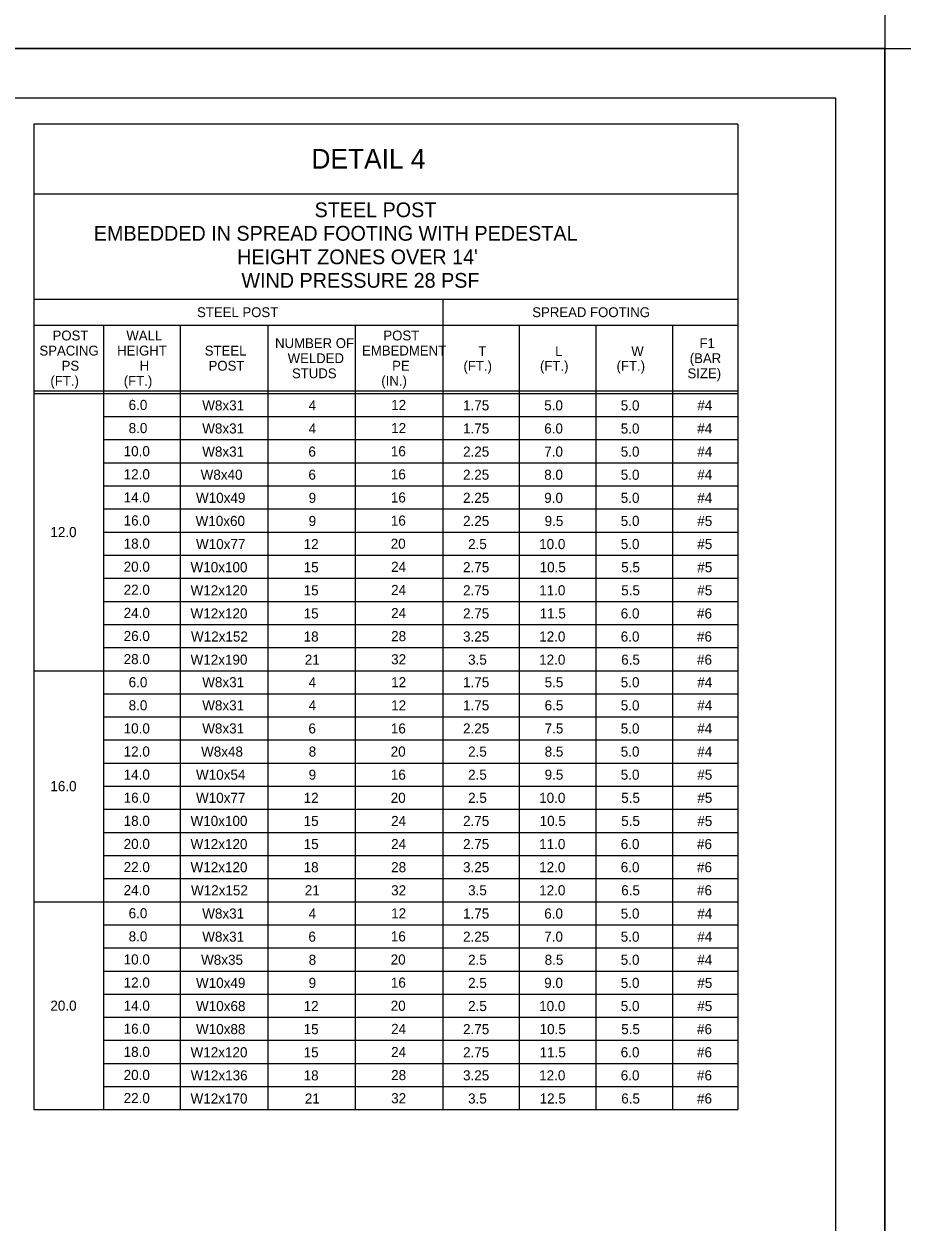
# Model space of a CAD drawing. Extents: x 3475 to 6558, y -3780 to 1166.
# Drawn here: x 5180.9 to 5448.6, y -2161.9 to -1796.8 of the extents above; entities that cross this region are included whole.
import ezdxf

# ---------------------------------------------------------------- set-up
doc = ezdxf.new("R2010")
doc.units = 0
for name, color, linetype in [('1', 7, 'Continuous'), ('2', 7, 'Continuous'), ('PLT-BNDY', 7, 'Continuous')]:
    doc.layers.add(name, color=color, linetype=linetype)

msp = doc.modelspace()

# ---------------------------------------------------------------- linework, layer by layer
at = {"layer": '1'}
for p, q in [((5183.95, -1827.3), (5183.95, -2127.63)), ((5398.61, -1827.3), (5183.95, -1827.3)), ((5398.61, -1827.3), (5398.61, -2127.63)), ((5398.61, -1848.64), (5183.95, -1848.64)), ((5183.95, -1880.64), (5398.61, -1880.64)), ((5308.61, -1880.64), (5308.61, -2127.63)), ((5183.95, -1888.64), (5251.95, -1888.64)), ((5183.95, -1888.64), (5398.61, -1888.64)), ((5205.28, -2127.63), (5205.28, -1888.64)), ((5228.61, -1888.64), (5228.61, -2127.63)), ((5255.28, -1888.64), (5255.28, -2127.63)), ((5281.95, -1888.64), (5281.95, -2127.63)), ((5331.95, -1888.64), (5331.95, -2127.63)), ((5355.28, -1888.64), (5355.28, -2127.63)), ((5378.61, -1888.64), (5378.61, -2127.63)), ((5183.95, -1908.64), (5398.61, -1908.64)), ((5183.95, -1909.39), (5398.61, -1909.39)), ((5205.28, -1916.43), (5398.61, -1916.43)), ((5205.28, -1923.47), (5398.61, -1923.47)), ((5205.28, -1930.51), (5398.61, -1930.51)), ((5205.28, -1937.55), (5398.61, -1937.55)), ((5205.28, -1944.59), (5398.61, -1944.59)), ((5205.28, -1951.63), (5398.61, -1951.63)), ((5205.28, -1958.67), (5398.61, -1958.67)), ((5205.28, -1965.71), (5398.61, -1965.71)), ((5205.28, -1972.75), (5398.61, -1972.75)), ((5205.28, -1979.79), (5398.61, -1979.79)), ((5205.28, -1986.83), (5398.61, -1986.83)), ((5183.95, -1993.87), (5398.61, -1993.87)), ((5205.28, -2000.91), (5398.61, -2000.91)), ((5205.28, -2007.95), (5398.61, -2007.95)), ((5205.28, -2014.99), (5398.61, -2014.99)), ((5205.28, -2022.03), (5398.61, -2022.03)), ((5205.28, -2029.07), (5398.61, -2029.07)), ((5205.28, -2036.11), (5398.61, -2036.11)), ((5205.28, -2043.15), (5398.61, -2043.15)), ((5205.28, -2050.19), (5398.61, -2050.19)), ((5205.28, -2057.23), (5398.61, -2057.23)), ((5183.95, -2064.27), (5398.61, -2064.27)), ((5205.28, -2071.31), (5398.61, -2071.31)), ((5205.28, -2078.35), (5398.61, -2078.35)), ((5205.28, -2085.39), (5398.61, -2085.39)), ((5205.28, -2092.43), (5398.61, -2092.43)), ((5205.28, -2099.47), (5398.61, -2099.47)), ((5205.28, -2106.51), (5398.61, -2106.51)), ((5205.28, -2113.55), (5398.61, -2113.55)), ((5205.28, -2120.59), (5398.61, -2120.59)), ((5183.95, -2127.63), (5398.61, -2127.63))]:
    msp.add_line(p, q, dxfattribs=at)
at = {"layer": '2'}
for p, q in [((4642.34, -1819.31), (5428.34, -1819.31)), ((5428.34, -1819.31), (5428.34, -2383.31))]:
    msp.add_line(p, q, dxfattribs=at)
at = {"layer": 'PLT-BNDY'}
for points in [[(4602.34, -1210.31), (5443.34, -1210.31), (5443.34, -1804.31), (4602.34, -1804.31)], [(4602.34, -1804.31), (5443.34, -1804.31), (5443.34, -2398.31), (4602.34, -2398.31)], [(5443.34, -1804.31), (6284.34, -1804.31), (6284.34, -2398.31), (5443.34, -2398.31)]]:
    msp.add_lwpolyline(points, close=True, dxfattribs=at)

# ---------------------------------------------------------------- texts
at = {"layer": '1'}
for s, height, p in [('DETAIL 4', 6, (5268.58, -1840.89)), ('STEEL POST', 4.5, (5269.54, -1855.69)), ('EMBEDDED IN SPREAD FOOTING WITH PEDESTAL', 4.5001, (5202.25, -1862.85)), ("HEIGHT ZONES OVER 14'", 4.5001, (5245.93, -1870.02)), ('WIND PRESSURE 28 PSF', 4.5001, (5247.24, -1877.19)), ('STEEL POST', 3, (5233.72, -1886.14)), ('SPREAD FOOTING', 3, (5335.9, -1886.14)), ('POST', 3, (5189.67, -1893.24)), ('WALL', 3, (5212.16, -1893.24)), ('POST', 3, (5290.52, -1893.24)), ('NUMBER OF', 3, (5257.5, -1895.56)), ('F1', 3, (5386.87, -1895.56)), ('SPACING', 3, (5185.67, -1897.84)), ('HEIGHT', 3, (5209.34, -1897.84)), ('STEEL', 3, (5236.05, -1897.86)), ('WELDED', 3, (5261.34, -1900.16)), ('EMBEDMENT', 3, (5284.02, -1897.84)), ('T', 3, (5319.42, -1898)), ('L', 3, (5342.88, -1898)), ('W', 3, (5366.08, -1898)), ('(BAR', 3, (5383.91, -1900.16)), ('PS', 3, (5192.43, -1902.44)), ('H', 3, (5216.21, -1902.44)), ('POST', 3, (5237.22, -1902.46)), ('STUDS', 3, (5262.65, -1904.76)), ('PE', 3, (5293.18, -1902.44)), ('(FT.)', 3, (5314.92, -1902.5)), ('(FT.)', 3, (5338.25, -1902.5)), ('(FT.)', 3, (5361.59, -1902.5)), ('SIZE)', 3, (5383.21, -1904.76)), ('(FT.)', 3, (5189, -1907.04)), ('(FT.)', 3, (5211.37, -1907.04)), ('(IN.)', 3, (5289.88, -1907.04)), ('6.0', 3.07, (5212.86, -1914.44)), ('W8x31', 3.07, (5235.29, -1914.56)), ('4', 3.07, (5267.74, -1914.56)), ('12', 3.07, (5292.88, -1914.44)), ('1.75', 3.07, (5314.8, -1914.56)), ('5.0', 3.07, (5339.54, -1914.56)), ('5.0', 3.07, (5362.87, -1914.58)), ('#4', 3.07, (5386.21, -1914.56)), ('8.0', 3.07, (5212.86, -1921.48)), ('W8x31', 3.07, (5235.29, -1921.6)), ('4', 3.07, (5267.74, -1921.6)), ('12', 3.07, (5292.88, -1921.49)), ('1.75', 3.07, (5314.8, -1921.6)), ('6.0', 3.07, (5339.54, -1921.6)), ('5.0', 3.07, (5362.87, -1921.62)), ('#4', 3.07, (5386.21, -1921.6)), ('10.0', 3.07, (5211.34, -1928.52)), ('W8x31', 3.07, (5235.29, -1928.65)), ('6', 3.07, (5267.66, -1928.65)), ('16', 3.07, (5292.79, -1928.54)), ('2.25', 3.07, (5314.8, -1928.65)), ('7.0', 3.07, (5339.54, -1928.65)), ('5.0', 3.07, (5362.87, -1928.66)), ('#4', 3.07, (5386.21, -1928.65)), ('12.0', 3.07, (5211.34, -1935.56)), ('W8x40', 3.07, (5234.8, -1935.69)), ('6', 3.07, (5267.66, -1935.69)), ('16', 3.07, (5292.79, -1935.58)), ('2.25', 3.07, (5314.8, -1935.69)), ('8.0', 3.07, (5339.54, -1935.69)), ('5.0', 3.07, (5362.87, -1935.7)), ('#4', 3.07, (5386.21, -1935.69)), ('14.0', 3.07, (5211.34, -1942.6)), ('W10x49', 3.07, (5233.39, -1942.74)), ('9', 3.07, (5267.73, -1942.74)), ('16', 3.07, (5292.79, -1942.63)), ('2.25', 3.07, (5314.8, -1942.74)), ('9.0', 3.07, (5339.54, -1942.74)), ('5.0', 3.07, (5362.87, -1942.74)), ('#4', 3.07, (5386.21, -1942.74)), ('16.0', 3.07, (5211.34, -1949.64)), ('W10x60', 3.07, (5233.27, -1949.78)), ('9', 3.07, (5267.73, -1949.78)), ('16', 3.07, (5292.79, -1949.67)), ('2.25', 3.07, (5314.8, -1949.78)), ('9.5', 3.07, (5339.67, -1949.78)), ('5.0', 3.07, (5362.87, -1949.78)), ('#5', 3.07, (5386.21, -1949.78)), ('12.0', 3.07, (5189, -1953.16)), ('18.0', 3.07, (5211.34, -1956.68)), ('W10x77', 3.07, (5233.4, -1956.83)), ('12', 3.07, (5266.21, -1956.83)), ('20', 3.07, (5292.74, -1956.71)), ('2.5', 3.07, (5316.34, -1956.83)), ('10.0', 3.07, (5338, -1956.83)), ('5.0', 3.07, (5362.87, -1956.83)), ('#5', 3.07, (5386.21, -1956.83)), ('20.0', 3.07, (5211.34, -1963.72)), ('W10x100', 3.07, (5231.73, -1963.87)), ('15', 3.07, (5266.21, -1963.87)), ('24', 3.07, (5292.88, -1963.77)), ('2.75', 3.07, (5314.8, -1963.87)), ('10.5', 3.07, (5338.14, -1963.87)), ('5.5', 3.07, (5363.01, -1963.87)), ('#5', 3.07, (5386.21, -1963.87)), ('22.0', 3.07, (5211.34, -1970.76)), ('24', 3.07, (5292.88, -1970.81)), ('W12x120', 3.07, (5231.73, -1970.91)), ('15', 3.07, (5266.21, -1970.91)), ('2.75', 3.07, (5314.8, -1970.91)), ('11.0', 3.07, (5338, -1970.91)), ('5.5', 3.07, (5363.01, -1970.91)), ('#5', 3.07, (5386.21, -1970.91)), ('24.0', 3.07, (5211.34, -1977.8)), ('W12x120', 3.07, (5231.73, -1977.96)), ('15', 3.07, (5266.21, -1977.96)), ('24', 3.07, (5292.88, -1977.85)), ('2.75', 3.07, (5314.8, -1977.96)), ('11.5', 3.07, (5338.14, -1977.96)), ('6.0', 3.07, (5362.87, -1977.96)), ('#6', 3.07, (5386.12, -1977.96)), ('26.0', 3.07, (5211.34, -1984.84)), ('W12x152', 3.07, (5231.87, -1985)), ('18', 3.07, (5266.21, -1985)), ('28', 3.07, (5292.88, -1984.88)), ('3.25', 3.07, (5314.8, -1985)), ('12.0', 3.07, (5338, -1985)), ('6.0', 3.07, (5362.87, -1985)), ('#6', 3.07, (5386.12, -1985)), ('28.0', 3.07, (5211.34, -1991.88)), ('W12x190', 3.07, (5231.73, -1992.05)), ('21', 3.07, (5266.56, -1992.05)), ('32', 3.07, (5292.88, -1991.93)), ('3.5', 3.07, (5316.34, -1992.05)), ('12.0', 3.07, (5338, -1992.05)), ('6.5', 3.07, (5363.01, -1992.05)), ('#6', 3.07, (5386.12, -1992.05)), ('6.0', 3.07, (5212.86, -1998.92)), ('W8x31', 3.07, (5235.29, -1998.92)), ('4', 3.07, (5267.74, -1998.92)), ('12', 3.07, (5292.88, -1998.92)), ('1.75', 3.07, (5314.8, -1998.92)), ('5.5', 3.07, (5339.67, -1998.92)), ('5.0', 3.07, (5362.87, -1998.94)), ('#4', 3.07, (5386.21, -1998.92)), ('8.0', 3.07, (5212.86, -2005.96)), ('W8x31', 3.07, (5235.29, -2005.97)), ('4', 3.07, (5267.74, -2005.97)), ('12', 3.07, (5292.88, -2005.97)), ('1.75', 3.07, (5314.8, -2005.97)), ('6.5', 3.07, (5339.67, -2005.97)), ('5.0', 3.07, (5362.87, -2005.98)), ('#4', 3.07, (5386.21, -2005.97)), ('10.0', 3.07, (5211.34, -2013)), ('W8x31', 3.07, (5235.29, -2013.01)), ('6', 3.07, (5267.66, -2013.01)), ('16', 3.07, (5292.79, -2013.01)), ('2.25', 3.07, (5314.8, -2013.01)), ('7.5', 3.07, (5339.67, -2013.01)), ('5.0', 3.07, (5362.87, -2013.02)), ('#4', 3.07, (5386.21, -2013.01)), ('12.0', 3.07, (5211.34, -2020.04)), ('W8x48', 3.07, (5234.94, -2020.06)), ('8', 3.07, (5267.74, -2020.06)), ('20', 3.07, (5292.74, -2020.06)), ('2.5', 3.07, (5316.34, -2020.06)), ('8.5', 3.07, (5339.67, -2020.06)), ('5.0', 3.07, (5362.87, -2020.06)), ('#4', 3.07, (5386.21, -2020.06)), ('14.0', 3.07, (5211.34, -2027.08)), ('W10x54', 3.07, (5233.4, -2027.1)), ('9', 3.07, (5267.73, -2027.1)), ('16', 3.07, (5292.79, -2027.1)), ('2.5', 3.07, (5316.34, -2027.1)), ('9.5', 3.07, (5339.67, -2027.1)), ('5.0', 3.07, (5362.87, -2027.1)), ('#5', 3.07, (5386.21, -2027.1)), ('16.0', 3.07, (5189, -2030.6)), ('16.0', 3.07, (5211.34, -2034.12)), ('W10x77', 3.07, (5233.4, -2034.15)), ('12', 3.07, (5266.21, -2034.15)), ('20', 3.07, (5292.74, -2034.15)), ('2.5', 3.07, (5316.34, -2034.15)), ('10.0', 3.07, (5338, -2034.15)), ('5.5', 3.07, (5363.01, -2034.15)), ('#5', 3.07, (5386.21, -2034.15)), ('18.0', 3.07, (5211.34, -2041.16)), ('W10x100', 3.07, (5231.73, -2041.19)), ('15', 3.07, (5266.21, -2041.19)), ('24', 3.07, (5292.88, -2041.2)), ('2.75', 3.07, (5314.8, -2041.19)), ('10.5', 3.07, (5338.14, -2041.19)), ('5.5', 3.07, (5363.01, -2041.19)), ('#5', 3.07, (5386.21, -2041.19)), ('20.0', 3.07, (5211.34, -2048.2)), ('W12x120', 3.07, (5231.73, -2048.24)), ('15', 3.07, (5266.21, -2048.24)), ('24', 3.07, (5292.88, -2048.24)), ('2.75', 3.07, (5314.8, -2048.24)), ('11.0', 3.07, (5338, -2048.24)), ('6.0', 3.07, (5362.87, -2048.24)), ('#6', 3.07, (5386.12, -2048.24)), ('22.0', 3.07, (5211.34, -2055.24)), ('W12x120', 3.07, (5231.73, -2055.28)), ('18', 3.07, (5266.21, -2055.28)), ('28', 3.07, (5292.88, -2055.28)), ('3.25', 3.07, (5314.8, -2055.28)), ('12.0', 3.07, (5338, -2055.28)), ('6.0', 3.07, (5362.87, -2055.28)), ('#6', 3.07, (5386.12, -2055.28)), ('24.0', 3.07, (5211.34, -2062.28)), ('W12x152', 3.07, (5231.87, -2062.32)), ('21', 3.07, (5266.56, -2062.32)), ('32', 3.07, (5292.88, -2062.33)), ('3.5', 3.07, (5316.34, -2062.32)), ('12.0', 3.07, (5338, -2062.32)), ('6.5', 3.07, (5363.01, -2062.32)), ('#6', 3.07, (5386.12, -2062.32)), ('6.0', 3.07, (5212.86, -2069.32)), ('W8x31', 3.07, (5235.29, -2069.41)), ('12', 3.07, (5292.88, -2069.33)), ('6.0', 3.07, (5339.54, -2069.41)), ('5.0', 3.07, (5362.87, -2069.42)), ('4', 3.07, (5267.74, -2069.41)), ('1.75', 3.07, (5314.8, -2069.41)), ('#4', 3.07, (5386.21, -2069.41)), ('8.0', 3.07, (5212.86, -2076.36)), ('W8x31', 3.07, (5235.29, -2076.45)), ('6', 3.07, (5267.66, -2076.45)), ('16', 3.07, (5292.79, -2076.37)), ('2.25', 3.07, (5314.8, -2076.45)), ('7.0', 3.07, (5339.54, -2076.45)), ('5.0', 3.07, (5362.87, -2076.46)), ('#4', 3.07, (5386.21, -2076.45)), ('10.0', 3.07, (5211.34, -2083.4)), ('W8x35', 3.07, (5234.94, -2083.5)), ('8', 3.07, (5267.74, -2083.5)), ('20', 3.07, (5292.74, -2083.42)), ('2.5', 3.07, (5316.34, -2083.5)), ('8.5', 3.07, (5339.67, -2083.5)), ('5.0', 3.07, (5362.87, -2083.5)), ('#4', 3.07, (5386.21, -2083.5)), ('12.0', 3.07, (5211.34, -2090.44)), ('W10x49', 3.07, (5233.39, -2090.54)), ('9', 3.07, (5267.73, -2090.54)), ('16', 3.07, (5292.79, -2090.46)), ('2.5', 3.07, (5316.34, -2090.54)), ('9.0', 3.07, (5339.54, -2090.54)), ('5.0', 3.07, (5362.87, -2090.54)), ('#5', 3.07, (5386.21, -2090.54)), ('20.0', 3.07, (5189, -2097.48)), ('14.0', 3.07, (5211.34, -2097.48)), ('W10x68', 3.07, (5233.4, -2097.59)), ('12', 3.07, (5266.21, -2097.59)), ('20', 3.07, (5292.74, -2097.51)), ('2.5', 3.07, (5316.34, -2097.59)), ('10.0', 3.07, (5338, -2097.59)), ('5.0', 3.07, (5362.87, -2097.59)), ('#5', 3.07, (5386.21, -2097.59)), ('16.0', 3.07, (5211.34, -2104.52)), ('W10x88', 3.07, (5233.4, -2104.63)), ('15', 3.07, (5266.21, -2104.63)), ('24', 3.07, (5292.88, -2104.56)), ('2.75', 3.07, (5314.8, -2104.63)), ('10.5', 3.07, (5338.14, -2104.63)), ('5.5', 3.07, (5363.01, -2104.63)), ('#6', 3.07, (5386.12, -2104.63)), ('18.0', 3.07, (5211.34, -2111.56)), ('W12x120', 3.07, (5231.73, -2111.68)), ('15', 3.07, (5266.21, -2111.68)), ('24', 3.07, (5292.88, -2111.6)), ('2.75', 3.07, (5314.8, -2111.68)), ('11.5', 3.07, (5338.14, -2111.68)), ('6.0', 3.07, (5362.87, -2111.68)), ('#6', 3.07, (5386.12, -2111.68)), ('20.0', 3.07, (5211.34, -2118.6)), ('W12x136', 3.07, (5231.78, -2118.72)), ('18', 3.07, (5266.21, -2118.72)), ('28', 3.07, (5292.88, -2118.64)), ('3.25', 3.07, (5314.8, -2118.72)), ('12.0', 3.07, (5338, -2118.72)), ('6.0', 3.07, (5362.87, -2118.72)), ('#6', 3.07, (5386.12, -2118.72)), ('22.0', 3.07, (5211.34, -2125.64)), ('W12x170', 3.07, (5231.73, -2125.77)), ('21', 3.07, (5266.56, -2125.77)), ('32', 3.07, (5292.88, -2125.69)), ('3.5', 3.07, (5316.34, -2125.77)), ('12.5', 3.07, (5338.14, -2125.77)), ('6.5', 3.07, (5363.01, -2125.77)), ('#6', 3.07, (5386.12, -2125.77))]:
    msp.add_text(s, height=height, dxfattribs=at).set_placement(p)

doc.saveas('drawing.dxf')
